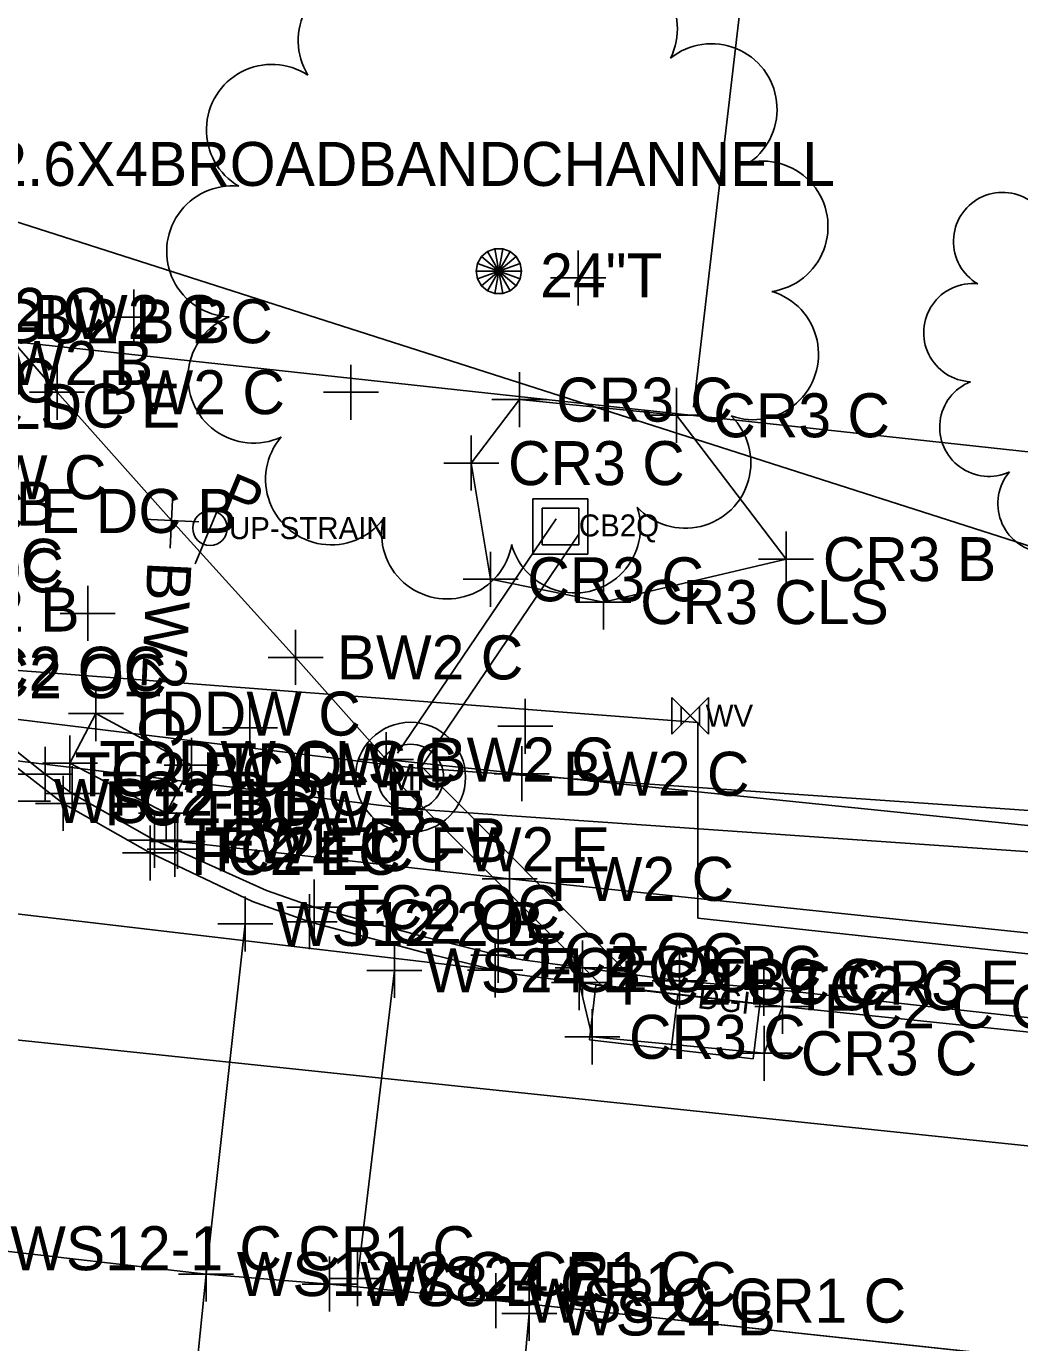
# Model space of a CAD drawing. Extents: x 1363693 to 1365209, y 422201 to 424153.
# Drawn here: x 1364278.52 to 1364314.62, y 423108.72 to 423156.57 of the extents above; entities that cross this region are included whole.
import ezdxf

# ---------------------------------------------------------------- set-up
doc = ezdxf.new("R2010")
doc.units = 0
for name, color, linetype in [('BASELINE-CL-RW', 7, 'Continuous'), ('DR_X_Cells', 7, 'Continuous'), ('DR_X_Storm_Sewer', 7, 'Continuous'), ('DR_X_Text', 7, 'Continuous'), ('O-ALGN-BASELINE-WERK-CL-RW', 7, 'Continuous'), ('O-ALGN-TEXT-BASELINE-WERK-CL-RW', 7, 'Continuous'), ('OWNERS', 7, 'Continuous'), ('PM_X_Channelizing_Line', 7, 'Continuous'), ('PM_X_Crosswalk', 7, 'Continuous'), ('PM_X_Stop_Line', 7, 'Continuous'), ('PV_P_Curb_Ramp', 7, 'Continuous'), ('RD_X_Misc_Items', 7, 'Continuous'), ('SV_X_Original_Ground', 7, 'Continuous'), ('SV_X_Shot_Marker', 7, 'Continuous'), ('UT_X_Misc_Cells', 7, 'Continuous'), ('UT_X_Sanitary_Line', 7, 'Continuous'), ('UT_X_Telecom', 7, 'Continuous'), ('UT_X_Unknown_Cells', 7, 'Continuous'), ('UT_X_Water', 7, 'Continuous'), ('UT_X_Water_Cells', 7, 'Continuous'), ('UT_X_Water_Text', 7, 'Continuous'), ('VG_X_Cells', 7, 'Continuous'), ('VG_X_Text', 7, 'Continuous')]:
    doc.layers.add(name, color=color, linetype=linetype)

msp = doc.modelspace()

# ---------------------------------------------------------------- linework, layer by layer
at = {"layer": 'BASELINE-CL-RW'}
msp.add_line((1364283.179, 423126.982), (1364280.185, 423128.678), dxfattribs=at)
msp.add_line((1364283.179, 423126.982), (1364280.185, 423128.678), dxfattribs=at)
for points in [[(1364280.185, 423128.678), (1364279.204, 423129.379), (1364276.322, 423131.689), (1364276.322, 423131.689), (1364274.681, 423133.216), (1364274.681, 423133.216), (1364271.987, 423136.004), (1364271.987, 423136.004), (1364270.945, 423137.141), (1364270.945, 423137.141), (1364270.595, 423137.599), (1364270.595, 423137.599), (1364269.75, 423138.952), (1364269.75, 423138.952)], [(1364320.859, 423119.872), (1364305.316, 423121.601), (1364302.257, 423121.869), (1364298.733, 423122.342), (1364296.547, 423122.635), (1364296.547, 423122.635), (1364295.67, 423122.804), (1364295.67, 423122.804), (1364293.025, 423123.46), (1364293.025, 423123.46), (1364288.986, 423124.55), (1364288.986, 423124.55), (1364287.251, 423125.15), (1364287.251, 423125.15), (1364283.916, 423126.658), (1364283.916, 423126.658), (1364283.179, 423126.982)]]:
    msp.add_lwpolyline(points, dxfattribs=at)
at = {"layer": 'DR_X_Cells'}
for p, q in [((1364296.931, 423139.387), (1364298.931, 423139.387)), ((1364296.931, 423139.387), (1364296.931, 423137.387)), ((1364298.931, 423139.387), (1364298.931, 423137.387)), ((1364297.264, 423137.72), (1364297.264, 423139.054)), ((1364297.264, 423139.054), (1364298.598, 423139.054)), ((1364298.598, 423139.054), (1364298.598, 423137.72)), ((1364298.931, 423137.387), (1364296.931, 423137.387)), ((1364298.598, 423137.72), (1364297.264, 423137.72)), ((1364299.212, 423121.717), (1364298.98, 423119.731)), ((1364299.212, 423121.717), (1364305.172, 423121.019)), ((1364301.959, 423119.382), (1364302.192, 423121.368)), ((1364305.172, 423121.019), (1364304.939, 423119.033)), ((1364304.939, 423119.033), (1364298.98, 423119.731))]:
    msp.add_line(p, q, dxfattribs=at)
at = {"layer": 'DR_X_Storm_Sewer'}
for p, q in [((1364297.772, 423138.664), (1364292.01, 423130.151)), ((1364298.6, 423138.104), (1364292.838, 423129.59)), ((1364300.358, 423122.175), (1364292.854, 423129.683)), ((1364299.65, 423121.468), (1364292.146, 423128.976))]:
    msp.add_line(p, q, dxfattribs=at)
for points in [[(1364396.704, 423122.381), (1364292.466, 423129.632), (1364116.736, 423151.168)], [(1364116.553, 423149.679), (1364292.322, 423128.138), (1364396.6, 423120.885)]]:
    msp.add_lwpolyline(points, dxfattribs=at)
at = {"layer": 'O-ALGN-BASELINE-WERK-CL-RW'}
for points in [[(1363946.375, 423147.199), (1363971.317, 423144.667), (1363995.58, 423142.128), (1364021.135, 423139.461), (1364045.823, 423136.819), (1364070.743, 423134.279), (1364095.743, 423131.549), (1364120.337, 423128.876), (1364145.279, 423126.289), (1364170.549, 423123.503), (1364184.679, 423122.2), (1364194.698, 423121.631), (1364223.029, 423118.455), (1364241.587, 423116.486), (1364258.097, 423114.418), (1364276.821, 423112.152), (1364285.05, 423111.214), (1364289.541, 423110.849), (1364295.586, 423110.248), (1364319.585, 423107.658), (1364345.02, 423104.847), (1364369.674, 423102.16)], [(1364306.127, 423137.202), (1364302.146, 423142.429), (1364296.44, 423142.998), (1364294.689, 423140.691), (1364295.389, 423136.467), (1364299.489, 423135.64), (1364306.127, 423137.202)], [(1364184.826, 423134.603), (1364224.316, 423130.683), (1364242.388, 423128.438), (1364258.919, 423126.573), (1364295.558, 423122.265)], [(1364305.998, 423120.944), (1364305.327, 423119.239), (1364299.085, 423119.837), (1364298.61, 423121.807)]]:
    msp.add_lwpolyline(points, dxfattribs=at)
at = {"layer": 'O-ALGN-TEXT-BASELINE-WERK-CL-RW'}
for points in [[(1364321.549, 423126.841), (1364296.522, 423129.399), (1364291.593, 423129.917), (1364288.303, 423133.628), (1364283.795, 423138.603), (1364279.64, 423143.27), (1364277.256, 423145.997), (1364278.44, 423161.186), (1364280.967, 423186.048)], [(1364320.915, 423122.985), (1364296.084, 423125.578), (1364284.015, 423126.938), (1364283.916, 423126.658)]]:
    msp.add_lwpolyline(points, dxfattribs=at)
at = {"layer": 'OWNERS'}
msp.add_lwpolyline([(1364320.806, 423119.405), (1364305.998, 423120.944), (1364298.61, 423121.807), (1364296.443, 423122.096), (1364296.443, 423122.096), (1364295.558, 423122.265), (1364295.558, 423122.265), (1364293.051, 423122.882), (1364293.051, 423122.882), (1364288.812, 423124.022), (1364288.812, 423124.022), (1364286.745, 423124.751), (1364286.745, 423124.751), (1364283.015, 423126.524), (1364283.015, 423126.524), (1364279.856, 423128.323), (1364276.387, 423131.012)], dxfattribs=at)
at = {"layer": 'PM_X_Channelizing_Line'}
for p, q in [((1364286.477, 423123.942), (1364285.05, 423111.214)), ((1364291.896, 423122.252), (1364290.55, 423111.048)), ((1364285.05, 423111.214), (1364283.924, 423100.028)), ((1364289.541, 423110.849), (1364295.586, 423110.248)), ((1364289.541, 423110.849), (1364295.586, 423110.248)), ((1364295.586, 423110.248), (1364319.585, 423107.658)), ((1364295.586, 423110.248), (1364319.585, 423107.658)), ((1364296.795, 423109.781), (1364295.77, 423098.35))]:
    msp.add_line(p, q, dxfattribs=at)
at = {"layer": 'PM_X_Crosswalk'}
for p, q in [((1364286.477, 423123.942), (1364285.05, 423111.214)), ((1364285.05, 423111.214), (1364283.924, 423100.028))]:
    msp.add_line(p, q, dxfattribs=at)
at = {"layer": 'PM_X_Stop_Line'}
for p, q in [((1364291.896, 423122.252), (1364290.55, 423111.048)), ((1364296.795, 423109.781), (1364295.77, 423098.35))]:
    msp.add_line(p, q, dxfattribs=at)
at = {"layer": 'PV_P_Curb_Ramp'}
for p, q in [((1364281.047, 423131.586), (1364280.105, 423129.789)), ((1364284.528, 423129.711), (1364281.047, 423131.586)), ((1364280.105, 423129.789), (1364283.596, 423127.967)), ((1364283.596, 423127.967), (1364284.528, 423129.711))]:
    msp.add_line(p, q, dxfattribs=at)
at = {"layer": 'RD_X_Misc_Items'}
for p, q in [((1364281.047, 423131.586), (1364280.105, 423129.789)), ((1364284.528, 423129.711), (1364281.047, 423131.586)), ((1364280.105, 423129.789), (1364283.596, 423127.967)), ((1364283.596, 423127.967), (1364284.528, 423129.711))]:
    msp.add_line(p, q, dxfattribs=at)
at = {"layer": 'SV_X_Original_Ground'}
for p, q in [((1364298.574, 423146.425), (1364298.574, 423148.425)), ((1364297.574, 423147.425), (1364299.574, 423147.425)), ((1364282.424, 423144.999), (1364282.424, 423146.999)), ((1364281.424, 423145.999), (1364283.424, 423145.999)), ((1364290.317, 423142.269), (1364290.317, 423144.269)), ((1364296.44, 423141.998), (1364296.44, 423143.998)), ((1364289.317, 423143.269), (1364291.317, 423143.269)), ((1364302.146, 423141.429), (1364302.146, 423143.429)), ((1364295.44, 423142.998), (1364297.44, 423142.998)), ((1364301.146, 423142.429), (1364303.146, 423142.429)), ((1364294.689, 423139.691), (1364294.689, 423141.691)), ((1364293.689, 423140.691), (1364295.689, 423140.691)), ((1364306.127, 423136.202), (1364306.127, 423138.202)), ((1364295.389, 423135.467), (1364295.389, 423137.467)), ((1364305.127, 423137.202), (1364307.127, 423137.202)), ((1364294.389, 423136.467), (1364296.389, 423136.467)), ((1364299.489, 423134.64), (1364299.489, 423136.64)), ((1364280.752, 423134.228), (1364280.752, 423136.228)), ((1364298.489, 423135.64), (1364300.489, 423135.64)), ((1364279.752, 423135.228), (1364281.752, 423135.228)), ((1364281.047, 423130.586), (1364281.047, 423132.586)), ((1364286.645, 423130.069), (1364286.645, 423132.069)), ((1364296.651, 423130.128), (1364296.651, 423132.128)), ((1364280.047, 423131.586), (1364282.047, 423131.586)), ((1364295.651, 423131.128), (1364297.651, 423131.128)), ((1364280.105, 423128.789), (1364280.105, 423130.789)), ((1364284.528, 423128.711), (1364284.528, 423130.711)), ((1364285.645, 423131.069), (1364287.645, 423131.069)), ((1364279.105, 423129.789), (1364281.105, 423129.789)), ((1364283.528, 423129.711), (1364285.528, 423129.711)), ((1364283.596, 423126.967), (1364283.596, 423128.967)), ((1364277.401, 423128.407), (1364279.401, 423128.407)), ((1364282.596, 423127.967), (1364284.596, 423127.967)), ((1364286.477, 423122.942), (1364286.477, 423124.942)), ((1364285.477, 423123.942), (1364287.477, 423123.942)), ((1364291.896, 423121.252), (1364291.896, 423123.252)), ((1364290.896, 423122.252), (1364292.896, 423122.252)), ((1364299.085, 423118.837), (1364299.085, 423120.837)), ((1364298.085, 423119.837), (1364300.085, 423119.837)), ((1364285.05, 423110.214), (1364285.05, 423112.214)), ((1364290.55, 423110.048), (1364290.55, 423112.048)), ((1364289.541, 423109.849), (1364289.541, 423111.849)), ((1364284.05, 423111.214), (1364286.05, 423111.214)), ((1364289.55, 423111.048), (1364291.55, 423111.048)), ((1364295.586, 423109.248), (1364295.586, 423111.248)), ((1364288.541, 423110.849), (1364290.541, 423110.849)), ((1364296.795, 423108.781), (1364296.795, 423110.781)), ((1364294.586, 423110.248), (1364296.586, 423110.248)), ((1364295.795, 423109.781), (1364297.795, 423109.781))]:
    msp.add_line(p, q, dxfattribs=at)
at = {"layer": 'SV_X_Shot_Marker'}
for p, q in [((1364279.64, 423142.27), (1364279.64, 423144.27)), ((1364278.64, 423143.27), (1364280.64, 423143.27)), ((1364283.842, 423139.602), (1364283.748, 423137.604)), ((1364282.796, 423138.65), (1364284.794, 423138.556)), ((1364288.303, 423132.628), (1364288.303, 423134.628)), ((1364287.303, 423133.628), (1364289.303, 423133.628)), ((1364291.593, 423128.917), (1364291.593, 423130.917)), ((1364279.204, 423128.379), (1364279.204, 423130.379)), ((1364296.522, 423128.399), (1364296.522, 423130.399)), ((1364280.185, 423127.678), (1364280.185, 423129.678)), ((1364290.593, 423129.917), (1364292.593, 423129.917)), ((1364278.204, 423129.379), (1364280.204, 423129.379)), ((1364279.856, 423127.323), (1364279.856, 423129.323)), ((1364295.522, 423129.399), (1364297.522, 423129.399)), ((1364278.856, 423128.323), (1364280.856, 423128.323)), ((1364279.185, 423128.678), (1364281.185, 423128.678)), ((1364283.179, 423125.982), (1364283.179, 423127.982)), ((1364284.015, 423125.938), (1364284.015, 423127.938)), ((1364283.015, 423125.524), (1364283.015, 423127.524)), ((1364283.916, 423125.658), (1364283.916, 423127.658)), ((1364282.179, 423126.982), (1364284.179, 423126.982)), ((1364283.015, 423126.938), (1364285.015, 423126.938)), ((1364282.015, 423126.524), (1364284.015, 423126.524)), ((1364282.916, 423126.658), (1364284.916, 423126.658)), ((1364296.084, 423124.578), (1364296.084, 423126.578)), ((1364288.986, 423123.55), (1364288.986, 423125.55)), ((1364295.084, 423125.578), (1364297.084, 423125.578)), ((1364288.812, 423123.022), (1364288.812, 423125.022)), ((1364287.986, 423124.55), (1364289.986, 423124.55)), ((1364287.812, 423124.022), (1364289.812, 423124.022)), ((1364295.67, 423121.804), (1364295.67, 423123.804)), ((1364295.558, 423121.265), (1364295.558, 423123.265)), ((1364298.733, 423121.342), (1364298.733, 423123.342)), ((1364294.67, 423122.804), (1364296.67, 423122.804)), ((1364298.61, 423120.807), (1364298.61, 423122.807)), ((1364302.257, 423120.869), (1364302.257, 423122.869)), ((1364305.316, 423120.601), (1364305.316, 423122.601)), ((1364294.558, 423122.265), (1364296.558, 423122.265)), ((1364297.733, 423122.342), (1364299.733, 423122.342)), ((1364297.61, 423121.807), (1364299.61, 423121.807)), ((1364301.257, 423121.869), (1364303.257, 423121.869)), ((1364304.316, 423121.601), (1364306.316, 423121.601)), ((1364305.998, 423119.944), (1364305.998, 423121.944)), ((1364304.998, 423120.944), (1364306.998, 423120.944)), ((1364305.327, 423118.239), (1364305.327, 423120.239)), ((1364304.327, 423119.239), (1364306.327, 423119.239))]:
    msp.add_line(p, q, dxfattribs=at)
at = {"layer": 'UT_X_Sanitary_Line'}
msp.add_line((1364304.832, 423160.399), (1364302.763, 423142.731), dxfattribs=at)
msp.add_lwpolyline([(1364693.403, 423102.755), (1364519.502, 423118.915), (1364254.219, 423147.686), (1364120.797, 423178.489), (1364080.299, 423181.531), (1364078.775, 423157.716), (1364068.834, 423074.38), (1364132.412, 423042.257), (1364111.643, 422924.766), (1364032.031, 422957.358)], dxfattribs=at)
at = {"layer": 'UT_X_Telecom'}
msp.add_lwpolyline([(1364331.133, 423132.499), (1364271.573, 423151.567), (1364307.701, 423558.666)], dxfattribs=at)
at = {"layer": 'UT_X_Unknown_Cells'}
msp.add_line((1364284.661, 423137.034), (1364285.464, 423138.979), dxfattribs=at)
for centre, radius in [((1364285.195, 423138.328), 0.63), ((1364292.483, 423129.271), 2), ((1364292.483, 423129.271), 1.2)]:
    msp.add_circle(centre, radius, dxfattribs=at)
at = {"layer": 'UT_X_Water'}
for p, q in [((1364302.315, 423131.173), (1364302.98, 423131.839)), ((1364302.315, 423131.839), (1364302.98, 423131.173)), ((1364302.315, 423131.839), (1364302.315, 423131.173)), ((1364302.98, 423131.839), (1364302.98, 423131.173))]:
    msp.add_line(p, q, dxfattribs=at)
for points in [[(1363797.978, 423165.496), (1364047.142, 423141.995), (1364047.135, 423142.005), (1364251.213, 423122.543), (1364692.365, 423076.33)], [(1364199.274, 423140.77), (1364264.462, 423134.201), (1364302.919, 423131.268), (1364302.919, 423124.149), (1364488.328, 423104.035), (1364526.667, 423100.332), (1364656.437, 423088.194), (1364694.224, 423084.44)]]:
    msp.add_lwpolyline(points, dxfattribs=at)
at = {"layer": 'UT_X_Water_Cells'}
for p, q in [((1364301.982, 423130.841), (1364303.312, 423132.171)), ((1364301.982, 423132.171), (1364303.312, 423130.841)), ((1364301.982, 423132.171), (1364301.982, 423130.841)), ((1364303.312, 423132.171), (1364303.312, 423130.841))]:
    msp.add_line(p, q, dxfattribs=at)
at = {"layer": 'VG_X_Cells'}
for points in [[(1364295.28, 423148.381), (1364295.692, 423147.667), (1364295.692, 423147.667), (1364295.061, 423148.197)], [(1364295.549, 423148.479), (1364295.692, 423147.667), (1364295.692, 423147.667), (1364295.28, 423148.381)], [(1364295.835, 423148.479), (1364295.692, 423147.667), (1364295.692, 423147.667), (1364295.549, 423148.479)], [(1364296.104, 423148.381), (1364295.692, 423147.667), (1364295.692, 423147.667), (1364295.835, 423148.479)], [(1364296.323, 423148.197), (1364295.692, 423147.667), (1364295.692, 423147.667), (1364296.104, 423148.381)], [(1364294.918, 423147.949), (1364295.692, 423147.667), (1364295.692, 423147.667), (1364294.868, 423147.667)], [(1364295.061, 423148.197), (1364295.692, 423147.667), (1364295.692, 423147.667), (1364294.918, 423147.949)], [(1364296.466, 423147.949), (1364295.692, 423147.667), (1364295.692, 423147.667), (1364296.323, 423148.197)], [(1364296.516, 423147.667), (1364295.692, 423147.667), (1364295.692, 423147.667), (1364296.466, 423147.949)], [(1364294.868, 423147.667), (1364295.692, 423147.667), (1364295.692, 423147.667), (1364294.918, 423147.385)], [(1364294.918, 423147.385), (1364295.692, 423147.667), (1364295.692, 423147.667), (1364295.061, 423147.137)], [(1364295.061, 423147.137), (1364295.692, 423147.667), (1364295.692, 423147.667), (1364295.28, 423146.953)], [(1364295.28, 423146.953), (1364295.692, 423147.667), (1364295.692, 423147.667), (1364295.549, 423146.855)], [(1364295.549, 423146.855), (1364295.692, 423147.667), (1364295.692, 423147.667), (1364295.835, 423146.855)], [(1364295.835, 423146.855), (1364295.692, 423147.667), (1364295.692, 423147.667), (1364296.104, 423146.953)], [(1364296.104, 423146.953), (1364295.692, 423147.667), (1364295.692, 423147.667), (1364296.323, 423147.137)], [(1364296.323, 423147.137), (1364295.692, 423147.667), (1364295.692, 423147.667), (1364296.466, 423147.385)], [(1364296.466, 423147.385), (1364295.692, 423147.667), (1364295.692, 423147.667), (1364296.516, 423147.667)]]:
    msp.add_lwpolyline(points, close=True, dxfattribs=at)
for centre, radius, start, end in [((1364290.779, 423156.05), 2.381, 28.9333, 211.816), ((1364299.8, 423156.472), 2.381, 333.5487, 156.4314), ((1364303.421, 423153.555), 2.381, 305.8564, 128.7391), ((1364287.446, 423152.806), 2.381, 56.6256, 239.5083), ((1364305.272, 423149.288), 2.381, 278.1641, 101.0468), ((1364286.002, 423148.385), 2.381, 84.3179, 267.2006), ((1364313.999, 423148.748), 1.786, 56.6256, 239.5083), ((1364304.928, 423144.65), 2.381, 250.4718, 73.3545), ((1364312.916, 423145.433), 1.786, 84.3179, 267.2006), ((1364286.778, 423143.8), 2.381, 112.0103, 294.8929), ((1364313.498, 423141.994), 1.786, 112.0103, 294.8929), ((1364302.468, 423140.704), 2.381, 222.7795, 45.6622), ((1364289.596, 423140.101), 2.381, 139.7026, 322.5852), ((1364315.611, 423139.219), 1.786, 139.7026, 322.5852), ((1364298.456, 423138.352), 2.381, 195.0872, 17.9699), ((1364293.811, 423138.134), 2.381, 167.3949, 350.2776)]:
    msp.add_arc(centre, radius, start, end, dxfattribs=at)

# ---------------------------------------------------------------- texts
at = {"layer": 'DR_X_Text'}
msp.add_text('CB2Q', height=0.8, dxfattribs=at).set_placement((1364298.599, 423138.025))
msp.add_text('DGI', height=0.8, rotation=353.3183, dxfattribs=at).set_placement((1364302.89, 423120.883))
at = {"layer": 'SV_X_Original_Ground'}
for s, p in [('UBX2.6X4BROADBANDCHANNELL', (1364272.951, 423150.767)), ('TDDW C', (1364271.041, 423142.892)), ('TDDW CLS', (1364269.276, 423141.933)), ('CR3 C', (1364297.777, 423142.198)), ('CR3 C', (1364303.483, 423141.629)), ('CR3 C', (1364296.026, 423139.891)), ('TDDW C', (1364272.877, 423139.38)), ('TDDW B', (1364271.122, 423138.422)), ('CR3 B', (1364307.464, 423136.402)), ('CR3 C', (1364296.726, 423135.667)), ('CR3 CLS', (1364300.826, 423134.84)), ('WS12-2 B', (1364270.706, 423134.57)), ('TDDW C', (1364282.118, 423130.786)), ('TDDW CLS', (1364281.176, 423128.989)), ('TDDW C', (1364285.599, 423128.911)), ('WS12-1 B', (1364279.52, 423127.607)), ('TDDW B', (1364284.667, 423127.167)), ('WS12-2 B', (1364287.596, 423123.142)), ('WS24 B', (1364293.015, 423121.452)), ('CR3 C', (1364300.422, 423119.037)), ('WS12-1 C CR1 C', (1364277.94, 423111.352)), ('WS12-2 C CR1 C', (1364286.169, 423110.414)), ('WS8 B CR1 C', (1364290.66, 423110.049)), ('WS24 E', (1364291.669, 423110.248)), ('WS8 C CR1 C', (1364296.705, 423109.448)), ('WS24 B', (1364297.914, 423108.981))]:
    msp.add_text(s, height=1.6, dxfattribs=at).set_placement(p)
at = {"layer": 'SV_X_Shot_Marker'}
for s, p in [('FW2 C', (1364274.72, 423145.458)), ('FC2 EC E GU2 B BC', (1364267.263, 423145.048)), ('BW2 C', (1364278.756, 423145.197)), ('TC2 OC FW2 B', (1364268.153, 423143.527)), ('BW2 C', (1364281.14, 423142.47)), ('TC2 B BC DC E', (1364268.777, 423141.981)), ('TC2 EC E DC B', (1364270.821, 423138.152)), ('TC2 OC', (1364272.016, 423136.341)), ('FC2 OC', (1364272.048, 423135.99)), ('TC2 OC', (1364275.752, 423132.416)), ('BW2 C', (1364289.803, 423132.828)), ('FC2 OC', (1364275.77, 423132.145)), ('BW2 C', (1364293.093, 423129.117)), ('TC2 BC', (1364280.275, 423128.579)), ('BW2 C', (1364298.022, 423128.599)), ('TC2 B DC E', (1364281.256, 423127.878)), ('FC2 BC', (1364281.356, 423127.523)), ('TC2 E DC B', (1364284.25, 423126.182)), ('FW2 C', (1364285.515, 423126.138)), ('FC2 EC', (1364284.515, 423125.724)), ('TC2 EC FW2 E', (1364284.987, 423125.858)), ('FW2 C', (1364297.584, 423124.778)), ('TC2 OC', (1364290.057, 423123.75)), ('FC2 OC', (1364290.312, 423123.222)), ('TC2 OC', (1364296.741, 423122.004)), ('FC2 OC', (1364297.058, 423121.465)), ('TC2 BC', (1364299.804, 423121.542)), ('FC2 BC CR3 E', (1364300.11, 423121.007)), ('TC2 C', (1364303.328, 423121.069)), ('TC2 C', (1364306.387, 423120.801)), ('FC2 C CR3 B', (1364307.498, 423120.144)), ('CR3 C', (1364306.664, 423118.439))]:
    msp.add_text(s, height=1.6, dxfattribs=at).set_placement(p)
msp.add_text('BW2 C', height=1.6, rotation=267.3035, dxfattribs=at).set_placement((1364282.925, 423137.142))
at = {"layer": 'UT_X_Misc_Cells'}
msp.add_text('UP-STRAIN', height=0.8, dxfattribs=at).set_placement((1364285.884, 423137.928))
at = {"layer": 'UT_X_Unknown_Cells'}
msp.add_text('P', height=1.503, rotation=337.5827, dxfattribs=at).set_placement((1364285.464, 423138.979))
msp.add_text('MH', height=0.96, dxfattribs=at).set_placement((1364291.614, 423128.791))
at = {"layer": 'UT_X_Water_Text'}
msp.add_text('WV', height=0.8, dxfattribs=at).set_placement((1364303.207, 423131.106))
at = {"layer": 'VG_X_Text'}
msp.add_text('24"T', height=1.6, dxfattribs=at).set_placement((1364297.192, 423146.715))

doc.saveas('drawing.dxf')
